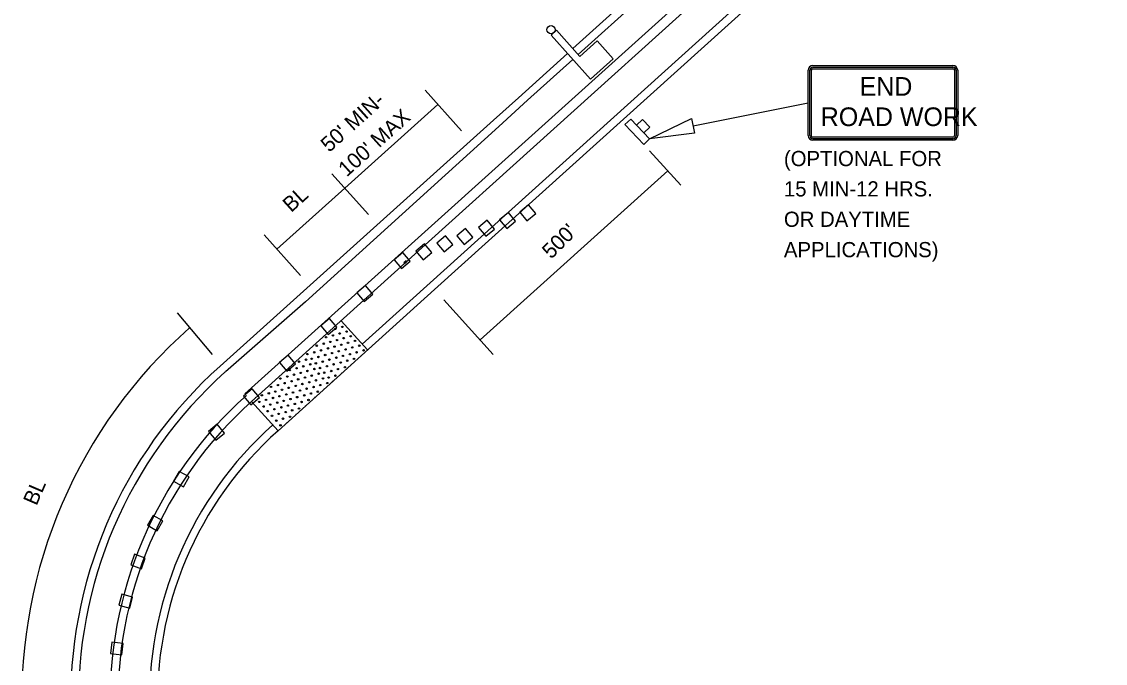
# Model space of a CAD drawing. Extents: x 1531.4 to 1538.6, y 1529.6 to 1539.7.
# Drawn here: x 1533.912 to 1538.193, y 1535.235 to 1537.771 of the extents above; entities that cross this region are included whole.
import ezdxf

# ---------------------------------------------------------------- set-up
doc = ezdxf.new("R2010")
doc.units = 0
for name, color, linetype in [('C-SIGN-FACE-N', 7, 'Continuous'), ('DETL-DIMS', 7, 'Continuous'), ('DETL-LINE', 7, 'Continuous'), ('DETL-NOTE', 7, 'Continuous')]:
    doc.layers.add(name, color=color, linetype=linetype)

msp = doc.modelspace()

# ---------------------------------------------------------------- linework, layer by layer
at = {"layer": 'C-SIGN-FACE-N'}
for p, q in [((1537.0377, 1537.5977), (1537.5916, 1537.5977)), ((1537.0377, 1537.5977), (1537.5916, 1537.5977)), ((1537.0377, 1537.5918), (1537.5916, 1537.5918)), ((1537.0377, 1537.5853), (1537.5916, 1537.5853)), ((1537.0194, 1537.3208), (1537.0194, 1537.5794)), ((1537.0253, 1537.3208), (1537.0253, 1537.5794)), ((1537.0318, 1537.3208), (1537.0318, 1537.5794)), ((1537.5975, 1537.5794), (1537.5975, 1537.3208)), ((1537.604, 1537.5794), (1537.604, 1537.3208)), ((1537.6099, 1537.5794), (1537.6099, 1537.3208)), ((1537.5916, 1537.3149), (1537.0377, 1537.3149)), ((1537.5916, 1537.3084), (1537.0377, 1537.3084)), ((1537.5916, 1537.3025), (1537.0377, 1537.3025))]:
    msp.add_line(p, q, dxfattribs=at)
for centre, radius, start, end in [((1537.0378, 1537.5793), 0.0185, 90, 180), ((1537.0378, 1537.5793), 0.0123, 90, 180), ((1537.0378, 1537.5793), 0.00615, 90, 180), ((1537.5914, 1537.5793), 0.0185, 0, 90), ((1537.5914, 1537.5793), 0.0123, 0, 90), ((1537.5914, 1537.5793), 0.00615, 0, 90), ((1537.0378, 1537.321), 0.0185, 180, 270), ((1537.0378, 1537.321), 0.0123, 180, 270), ((1537.0378, 1537.321), 0.00615, 180, 270), ((1537.5914, 1537.321), 0.0185, 270, 0), ((1537.5914, 1537.321), 0.0123, 270, 0), ((1537.5914, 1537.321), 0.00615, 270, 0)]:
    msp.add_arc(centre, radius, start, end, dxfattribs=at)
at = {"layer": 'DETL-DIMS'}
for p, q in [((1535.5054, 1537.5008), (1535.6495, 1537.3399)), ((1535.1882, 1537.1133), (1535.5561, 1537.4442)), ((1536.5642, 1537.3594), (1537.0194, 1537.4501)), ((1536.3924, 1537.2612), (1536.5157, 1537.1245)), ((1535.1375, 1537.1699), (1535.2816, 1537.009)), ((1535.7236, 1536.5133), (1536.4642, 1537.1817)), ((1534.9204, 1536.8724), (1535.1882, 1537.1133)), ((1534.8699, 1536.9288), (1535.0139, 1536.7678)), ((1535.58, 1536.6724), (1535.7751, 1536.4561)), ((1534.5257, 1536.6211), (1534.6645, 1536.4555))]:
    msp.add_line(p, q, dxfattribs=at)
msp.add_lwpolyline([(1536.5584, 1537.3888), (1536.5702, 1537.33), (1536.3921, 1537.3076)], close=True, dxfattribs=at)
msp.add_arc((1535.8737, 1535.091), 1.9621, 131.4354, 181.9604, dxfattribs=at)
at = {"layer": 'DETL-LINE'}
for p, q in [((1536.0895, 1537.6646), (1537.9623, 1539.3605)), ((1536.1102, 1537.6414), (1537.9832, 1539.3374)), ((1534.7936, 1536.3), (1538.0646, 1539.2471)), ((1535.4388, 1536.8288), (1538.0887, 1539.2203)), ((1535.2575, 1536.4968), (1538.1724, 1539.1276)), ((1535.5433, 1536.713), (1538.1933, 1539.1044)), ((1536.0037, 1537.7183), (1536.0248, 1537.7371)), ((1536.1593, 1537.544), (1536.0037, 1537.7183)), ((1536.0248, 1537.7371), (1536.1167, 1537.6341)), ((1536.1856, 1537.6956), (1536.1167, 1537.6341)), ((1536.2493, 1537.6244), (1536.1856, 1537.6956)), ((1535.875, 1537.4704), (1536.0685, 1537.6456)), ((1535.9104, 1537.4605), (1536.0893, 1537.6224)), ((1536.1593, 1537.544), (1536.2493, 1537.6244)), ((1535.7753, 1537.3814), (1535.875, 1537.4704)), ((1535.7968, 1537.3573), (1535.9104, 1537.4605)), ((1534.6953, 1536.4101), (1535.7753, 1537.3814)), ((1535.0336, 1536.6643), (1535.7968, 1537.3573)), ((1534.8202, 1536.2707), (1535.4388, 1536.8288)), ((1535.4206, 1536.8167), (1535.4206, 1536.8167)), ((1535.447, 1536.8244), (1535.447, 1536.8244)), ((1534.9247, 1536.1547), (1535.5433, 1536.713)), ((1535.2721, 1536.6827), (1535.2721, 1536.6827)), ((1535.0336, 1536.6643), (1534.7163, 1536.387)), ((1535.1511, 1536.5573), (1535.1511, 1536.5573)), ((1535.1737, 1536.5896), (1535.2782, 1536.4738)), ((1535.1782, 1536.5656), (1535.1782, 1536.5656)), ((1535.1787, 1536.565), (1535.1787, 1536.565)), ((1535.1143, 1536.5241), (1535.1143, 1536.5241)), ((1535.1143, 1536.5241), (1535.1143, 1536.5241)), ((1535.1247, 1536.5496), (1535.1247, 1536.5496)), ((1535.1408, 1536.5318), (1535.1408, 1536.5318)), ((1535.1413, 1536.5312), (1535.1413, 1536.5312)), ((1535.1574, 1536.5134), (1535.1574, 1536.5134)), ((1535.1579, 1536.5128), (1535.1579, 1536.5128)), ((1535.1677, 1536.5389), (1535.1677, 1536.5389)), ((1535.1844, 1536.5205), (1535.1844, 1536.5205)), ((1535.1948, 1536.5472), (1535.1948, 1536.5472)), ((1535.1953, 1536.5466), (1535.1953, 1536.5466)), ((1535.2119, 1536.5282), (1535.2119, 1536.5282)), ((1535.2119, 1536.5282), (1535.2119, 1536.5282)), ((1535.0775, 1536.4909), (1535.0775, 1536.4909)), ((1535.0941, 1536.4725), (1535.0941, 1536.4725)), ((1535.1045, 1536.4991), (1535.1045, 1536.4991)), ((1535.1051, 1536.4985), (1535.1051, 1536.4985)), ((1535.1212, 1536.4807), (1535.1212, 1536.4807)), ((1535.1217, 1536.4801), (1535.1217, 1536.4801)), ((1535.1309, 1536.5057), (1535.1309, 1536.5057)), ((1535.1309, 1536.5057), (1535.1309, 1536.5057)), ((1535.1475, 1536.4873), (1535.1475, 1536.4873)), ((1535.1475, 1536.4873), (1535.1475, 1536.4873)), ((1535.1642, 1536.4689), (1535.1642, 1536.4689)), ((1535.1642, 1536.4689), (1535.1642, 1536.4689)), ((1535.1745, 1536.4944), (1535.1745, 1536.4944)), ((1535.1745, 1536.4944), (1535.1745, 1536.4944)), ((1535.1911, 1536.476), (1535.1911, 1536.476)), ((1535.1911, 1536.476), (1535.1911, 1536.476)), ((1535.201, 1536.5021), (1535.201, 1536.5021)), ((1535.2176, 1536.4837), (1535.2176, 1536.4837)), ((1535.2286, 1536.5097), (1535.2286, 1536.5097)), ((1535.2286, 1536.5097), (1535.2286, 1536.5097)), ((1535.2452, 1536.4913), (1535.2452, 1536.4913)), ((1535.2457, 1536.4907), (1535.2457, 1536.4907)), ((1535.2618, 1536.4729), (1535.2618, 1536.4729)), ((1535.2623, 1536.4723), (1535.2623, 1536.4723)), ((1535.0076, 1536.4278), (1535.0076, 1536.4278)), ((1535.0346, 1536.436), (1535.0346, 1536.436)), ((1535.0351, 1536.4354), (1535.0351, 1536.4354)), ((1535.0407, 1536.4576), (1535.0407, 1536.4576)), ((1535.0407, 1536.4576), (1535.0407, 1536.4576)), ((1535.0573, 1536.4392), (1535.0573, 1536.4392)), ((1535.0573, 1536.4392), (1535.0573, 1536.4392)), ((1535.0671, 1536.4653), (1535.0671, 1536.4653)), ((1535.0677, 1536.4647), (1535.0677, 1536.4647)), ((1535.0837, 1536.4469), (1535.0837, 1536.4469)), ((1535.0843, 1536.4463), (1535.0843, 1536.4463)), ((1535.1009, 1536.4279), (1535.1009, 1536.4279)), ((1535.1009, 1536.4279), (1535.1009, 1536.4279)), ((1535.1107, 1536.454), (1535.1107, 1536.454)), ((1535.1273, 1536.4356), (1535.1273, 1536.4356)), ((1535.1383, 1536.4617), (1535.1383, 1536.4617)), ((1535.1383, 1536.4617), (1535.1383, 1536.4617)), ((1535.1549, 1536.4433), (1535.1549, 1536.4433)), ((1535.1549, 1536.4433), (1535.1549, 1536.4433)), ((1535.1808, 1536.4505), (1535.1808, 1536.4505)), ((1535.1808, 1536.4505), (1535.1808, 1536.4505)), ((1535.1979, 1536.4315), (1535.1979, 1536.4315)), ((1535.1979, 1536.4315), (1535.1979, 1536.4315)), ((1535.2078, 1536.4576), (1535.2078, 1536.4576)), ((1535.2083, 1536.457), (1535.2083, 1536.457)), ((1535.2244, 1536.4392), (1535.2244, 1536.4392)), ((1535.2249, 1536.4386), (1535.2249, 1536.4386)), ((1535.2347, 1536.4647), (1535.2347, 1536.4647)), ((1534.9707, 1536.3945), (1534.9707, 1536.3945)), ((1534.9707, 1536.3945), (1534.9707, 1536.3945)), ((1534.9811, 1536.42), (1534.9811, 1536.42)), ((1534.9972, 1536.4022), (1534.9972, 1536.4022)), ((1534.9977, 1536.4016), (1534.9977, 1536.4016)), ((1535.0138, 1536.3838), (1535.0138, 1536.3838)), ((1535.0143, 1536.3832), (1535.0143, 1536.3832)), ((1535.0242, 1536.4093), (1535.0242, 1536.4093)), ((1535.0408, 1536.3909), (1535.0408, 1536.3909)), ((1535.0512, 1536.4176), (1535.0512, 1536.4176)), ((1535.0518, 1536.417), (1535.0518, 1536.417)), ((1535.0684, 1536.3986), (1535.0684, 1536.3986)), ((1535.0684, 1536.3986), (1535.0684, 1536.3986)), ((1535.0739, 1536.4208), (1535.0739, 1536.4208)), ((1535.0739, 1536.4208), (1535.0739, 1536.4208)), ((1535.0905, 1536.4024), (1535.0905, 1536.4024)), ((1535.0905, 1536.4024), (1535.0905, 1536.4024)), ((1535.1071, 1536.384), (1535.1071, 1536.384)), ((1535.1071, 1536.384), (1535.1071, 1536.384)), ((1535.1175, 1536.4095), (1535.1175, 1536.4095)), ((1535.1175, 1536.4095), (1535.1175, 1536.4095)), ((1535.1341, 1536.3911), (1535.1341, 1536.3911)), ((1535.1347, 1536.3905), (1535.1347, 1536.3905)), ((1535.144, 1536.4172), (1535.144, 1536.4172)), ((1535.1611, 1536.3982), (1535.1611, 1536.3982)), ((1535.1715, 1536.4249), (1535.1715, 1536.4249)), ((1535.1721, 1536.4243), (1535.1721, 1536.4243)), ((1535.1882, 1536.4065), (1535.1882, 1536.4065)), ((1535.1887, 1536.4059), (1535.1887, 1536.4059)), ((1534.9336, 1536.361), (1534.9336, 1536.361)), ((1534.9502, 1536.3426), (1534.9502, 1536.3426)), ((1534.9607, 1536.3693), (1534.9607, 1536.3693)), ((1534.9612, 1536.3687), (1534.9612, 1536.3687)), ((1534.9773, 1536.3509), (1534.9773, 1536.3509)), ((1534.9778, 1536.3503), (1534.9778, 1536.3503)), ((1534.9874, 1536.3761), (1534.9874, 1536.3761)), ((1534.9874, 1536.3761), (1534.9874, 1536.3761)), ((1535.004, 1536.3577), (1535.004, 1536.3577)), ((1535.004, 1536.3577), (1535.004, 1536.3577)), ((1535.031, 1536.3648), (1535.031, 1536.3648)), ((1535.031, 1536.3648), (1535.031, 1536.3648)), ((1535.0476, 1536.3464), (1535.0476, 1536.3464)), ((1535.0476, 1536.3464), (1535.0476, 1536.3464)), ((1535.0574, 1536.3725), (1535.0574, 1536.3725)), ((1535.074, 1536.3541), (1535.074, 1536.3541)), ((1535.085, 1536.3802), (1535.085, 1536.3802)), ((1535.085, 1536.3802), (1535.085, 1536.3802)), ((1535.1016, 1536.3618), (1535.1016, 1536.3618)), ((1535.1021, 1536.3612), (1535.1021, 1536.3612)), ((1535.1182, 1536.3433), (1535.1182, 1536.3433)), ((1535.1188, 1536.3428), (1535.1188, 1536.3428)), ((1535.1243, 1536.365), (1535.1243, 1536.365)), ((1535.1243, 1536.365), (1535.1243, 1536.365)), ((1535.1507, 1536.3727), (1535.1507, 1536.3727)), ((1535.1513, 1536.3721), (1535.1513, 1536.3721)), ((1534.8875, 1536.3032), (1534.8875, 1536.3032)), ((1534.888, 1536.3026), (1534.888, 1536.3026)), ((1534.8968, 1536.3278), (1534.8968, 1536.3278)), ((1534.8968, 1536.3278), (1534.8968, 1536.3278)), ((1534.9134, 1536.3094), (1534.9134, 1536.3094)), ((1534.9134, 1536.3094), (1534.9134, 1536.3094)), ((1534.9233, 1536.3355), (1534.9233, 1536.3355)), ((1534.9238, 1536.3349), (1534.9238, 1536.3349)), ((1534.9399, 1536.3171), (1534.9399, 1536.3171)), ((1534.9404, 1536.3165), (1534.9404, 1536.3165)), ((1534.957, 1536.2981), (1534.957, 1536.2981)), ((1534.957, 1536.2981), (1534.957, 1536.2981)), ((1534.9669, 1536.3242), (1534.9669, 1536.3242)), ((1534.9835, 1536.3058), (1534.9835, 1536.3058)), ((1534.9944, 1536.3318), (1534.9944, 1536.3318)), ((1534.9944, 1536.3318), (1534.9944, 1536.3318)), ((1535.0111, 1536.3134), (1535.0111, 1536.3134)), ((1535.0111, 1536.3134), (1535.0111, 1536.3134)), ((1535.0206, 1536.3393), (1535.0206, 1536.3393)), ((1535.0206, 1536.3393), (1535.0206, 1536.3393)), ((1535.0372, 1536.3209), (1535.0372, 1536.3209)), ((1535.0372, 1536.3209), (1535.0372, 1536.3209)), ((1535.0544, 1536.3019), (1535.0544, 1536.3019)), ((1535.0544, 1536.3019), (1535.0544, 1536.3019)), ((1535.0642, 1536.328), (1535.0642, 1536.328)), ((1535.0647, 1536.3274), (1535.0647, 1536.3274)), ((1535.0808, 1536.3096), (1535.0808, 1536.3096)), ((1535.0813, 1536.309), (1535.0813, 1536.309)), ((1535.0912, 1536.3351), (1535.0912, 1536.3351)), ((1534.9247, 1536.1547), (1534.8202, 1536.2705)), ((1534.834, 1536.2872), (1534.834, 1536.2872)), ((1534.8501, 1536.2694), (1534.8501, 1536.2694)), ((1534.8506, 1536.2688), (1534.8506, 1536.2688)), ((1534.8604, 1536.295), (1534.8604, 1536.295)), ((1534.877, 1536.2765), (1534.877, 1536.2765)), ((1534.8937, 1536.2581), (1534.8937, 1536.2581)), ((1534.9041, 1536.2848), (1534.9041, 1536.2848)), ((1534.9046, 1536.2842), (1534.9046, 1536.2842)), ((1534.9212, 1536.2658), (1534.9212, 1536.2658)), ((1534.9212, 1536.2658), (1534.9212, 1536.2658)), ((1534.93, 1536.291), (1534.93, 1536.291)), ((1534.93, 1536.291), (1534.93, 1536.291)), ((1534.9466, 1536.2726), (1534.9466, 1536.2726)), ((1534.9466, 1536.2726), (1534.9466, 1536.2726)), ((1534.9736, 1536.2797), (1534.9736, 1536.2797)), ((1534.9736, 1536.2797), (1534.9736, 1536.2797)), ((1534.9903, 1536.2613), (1534.9903, 1536.2613)), ((1534.9908, 1536.2607), (1534.9908, 1536.2607)), ((1535.0001, 1536.2874), (1535.0001, 1536.2874)), ((1535.0172, 1536.2684), (1535.0172, 1536.2684)), ((1535.0277, 1536.295), (1535.0277, 1536.295)), ((1535.0282, 1536.2944), (1535.0282, 1536.2944)), ((1535.0443, 1536.2766), (1535.0443, 1536.2766)), ((1535.0448, 1536.276), (1535.0448, 1536.276)), ((1534.8667, 1536.251), (1534.8667, 1536.251)), ((1534.8672, 1536.2504), (1534.8672, 1536.2504)), ((1534.8838, 1536.232), (1534.8838, 1536.232)), ((1534.8838, 1536.232), (1534.8838, 1536.232)), ((1534.9004, 1536.2136), (1534.9004, 1536.2136)), ((1534.9004, 1536.2136), (1534.9004, 1536.2136)), ((1534.9103, 1536.2397), (1534.9103, 1536.2397)), ((1534.9269, 1536.2213), (1534.9269, 1536.2213)), ((1534.9379, 1536.2474), (1534.9379, 1536.2474)), ((1534.9379, 1536.2474), (1534.9379, 1536.2474)), ((1534.9545, 1536.229), (1534.9545, 1536.229)), ((1534.955, 1536.2284), (1534.955, 1536.2284)), ((1534.9633, 1536.2541), (1534.9633, 1536.2541)), ((1534.9633, 1536.2541), (1534.9633, 1536.2541)), ((1534.9804, 1536.2351), (1534.9804, 1536.2351)), ((1534.9804, 1536.2351), (1534.9804, 1536.2351)), ((1535.0069, 1536.2428), (1535.0069, 1536.2428)), ((1535.0074, 1536.2423), (1535.0074, 1536.2423)), ((1534.9171, 1536.1952), (1534.9171, 1536.1952)), ((1534.9176, 1536.1946), (1534.9176, 1536.1946)), ((1534.9337, 1536.1768), (1534.9337, 1536.1768)), ((1534.9342, 1536.1762), (1534.9342, 1536.1762)), ((1534.944, 1536.2023), (1534.944, 1536.2023)), ((1534.9711, 1536.2106), (1534.9711, 1536.2106)), ((1534.9716, 1536.21), (1534.9716, 1536.21))]:
    msp.add_line(p, q, dxfattribs=at)
for points in [[(1536.3179, 1537.3863), (1536.2954, 1537.3651), (1536.3696, 1537.2864), (1536.3921, 1537.3076)], [(1536.3409, 1537.3619), (1536.3693, 1537.3318), (1536.3931, 1537.3543), (1536.3647, 1537.3843)], [(1535.8794, 1537.0184), (1535.9082, 1536.9841), (1535.9425, 1537.0129), (1535.9137, 1537.0472)], [(1535.7166, 1536.9574), (1535.7454, 1536.9231), (1535.7797, 1536.9519), (1535.7509, 1536.9862)], [(1535.8002, 1536.9887), (1535.829, 1536.9544), (1535.8633, 1536.9832), (1535.8345, 1537.0175)], [(1535.6305, 1536.9252), (1535.6593, 1536.8909), (1535.6936, 1536.9197), (1535.6648, 1536.954)], [(1535.5523, 1536.8959), (1535.5811, 1536.8616), (1535.6154, 1536.8904), (1535.5866, 1536.9247)], [(1535.3835, 1536.8299), (1535.4124, 1536.7955), (1535.4467, 1536.8243), (1535.4178, 1536.8586)], [(1535.4688, 1536.8646), (1535.4976, 1536.8303), (1535.5319, 1536.8591), (1535.5031, 1536.8934)], [(1535.2363, 1536.6995), (1535.2652, 1536.6651), (1535.2995, 1536.6939), (1535.2706, 1536.7282)], [(1535.094, 1536.5691), (1535.1228, 1536.5347), (1535.1572, 1536.5635), (1535.1283, 1536.5978)], [(1534.9299, 1536.4242), (1534.9588, 1536.3898), (1534.9931, 1536.4186), (1534.9642, 1536.4529)], [(1534.7876, 1536.2913), (1534.8164, 1536.257), (1534.8507, 1536.2858), (1534.8219, 1536.3201)], [(1534.65, 1536.1513), (1534.6789, 1536.1169), (1534.7132, 1536.1457), (1534.6844, 1536.1801)], [(1534.5118, 1535.9555), (1534.5506, 1535.9331), (1534.573, 1535.9719), (1534.5342, 1535.9942)], [(1534.4081, 1535.7816), (1534.4469, 1535.7592), (1534.4693, 1535.798), (1534.4305, 1535.8203)], [(1534.3424, 1535.6246), (1534.3845, 1535.6093), (1534.3998, 1535.6514), (1534.3577, 1535.6666)], [(1534.2958, 1535.4649), (1534.3393, 1535.454), (1534.3501, 1535.4974), (1534.3067, 1535.5082)], [(1534.2625, 1535.2748), (1534.307, 1535.2692), (1534.3126, 1535.3136), (1534.2682, 1535.3192)]]:
    msp.add_lwpolyline(points, close=True, dxfattribs=at)
for points in [[(1535.4307, 1536.8256), (1535.4221, 1536.8179)], [(1535.2486, 1536.4469), (1535.251, 1536.4491)], [(1535.2117, 1536.4137), (1535.2142, 1536.4159)], [(1535.1381, 1536.3472), (1535.1405, 1536.3494)], [(1535.1749, 1536.3805), (1535.1773, 1536.3826)], [(1535.105, 1536.3174), (1535.1074, 1536.3196)], [(1535.0682, 1536.2842), (1535.0706, 1536.2864)], [(1534.9942, 1536.2174), (1534.9967, 1536.2196)], [(1535.0311, 1536.2506), (1535.0335, 1536.2528)], [(1534.9579, 1536.1846), (1534.9603, 1536.1868)]]:
    msp.add_lwpolyline(points, dxfattribs=at)
for centre, radius in [((1536.0031, 1537.7394), 0.0161), ((1535.1512, 1536.5573), 0.00291), ((1535.1787, 1536.565), 0.00291), ((1535.1143, 1536.5241), 0.00291), ((1535.1413, 1536.5312), 0.00291), ((1535.1579, 1536.5128), 0.00291), ((1535.1678, 1536.5389), 0.00291), ((1535.1844, 1536.5205), 0.00291), ((1535.1953, 1536.5465), 0.00291), ((1535.212, 1536.5281), 0.00291), ((1535.2286, 1536.5097), 0.00291), ((1535.0775, 1536.4908), 0.00291), ((1535.0941, 1536.4724), 0.00291), ((1535.1051, 1536.4985), 0.00291), ((1535.1217, 1536.4801), 0.00291), ((1535.1309, 1536.5057), 0.00291), ((1535.1476, 1536.4873), 0.00291), ((1535.1642, 1536.4688), 0.00291), ((1535.1745, 1536.4944), 0.00291), ((1535.1912, 1536.476), 0.00291), ((1535.201, 1536.5021), 0.00291), ((1535.2176, 1536.4837), 0.00291), ((1535.2457, 1536.4907), 0.00291), ((1535.2623, 1536.4723), 0.00291), ((1535.0076, 1536.4278), 0.00291), ((1535.0352, 1536.4354), 0.00291), ((1535.0407, 1536.4576), 0.00291), ((1535.0573, 1536.4392), 0.00291), ((1535.0676, 1536.4647), 0.00291), ((1535.0843, 1536.4463), 0.00291), ((1535.1009, 1536.4279), 0.00291), ((1535.1107, 1536.454), 0.00291), ((1535.1273, 1536.4356), 0.00291), ((1535.1383, 1536.4616), 0.00291), ((1535.1549, 1536.4432), 0.00291), ((1535.1721, 1536.4242), 0.00291), ((1535.1808, 1536.4504), 0.00291), ((1535.1979, 1536.4314), 0.00291), ((1535.2083, 1536.457), 0.00291), ((1535.2249, 1536.4385), 0.00291), ((1535.2348, 1536.4647), 0.00291), ((1534.9708, 1536.3945), 0.00291), ((1534.9978, 1536.4016), 0.00291), ((1535.0144, 1536.3832), 0.00291), ((1535.0242, 1536.4093), 0.00291), ((1535.0408, 1536.3909), 0.00291), ((1535.0518, 1536.417), 0.00291), ((1535.0684, 1536.3986), 0.00291), ((1535.0739, 1536.4208), 0.00291), ((1535.085, 1536.3802), 0.00291), ((1535.0905, 1536.4024), 0.00291), ((1535.1071, 1536.3839), 0.00291), ((1535.1175, 1536.4095), 0.00291), ((1535.1346, 1536.3905), 0.00291), ((1535.1439, 1536.4172), 0.00291), ((1535.1611, 1536.3982), 0.00291), ((1535.1887, 1536.4058), 0.00291), ((1534.9337, 1536.361), 0.00291), ((1534.9503, 1536.3426), 0.00291), ((1534.9612, 1536.3687), 0.00291), ((1534.9779, 1536.3503), 0.00291), ((1534.9874, 1536.3761), 0.00291), ((1535.004, 1536.3577), 0.00291), ((1535.0206, 1536.3393), 0.00291), ((1535.031, 1536.3648), 0.00291), ((1535.0476, 1536.3464), 0.00291), ((1535.0575, 1536.3725), 0.00291), ((1535.0741, 1536.3541), 0.00291), ((1535.1022, 1536.3612), 0.00291), ((1535.1188, 1536.3428), 0.00291), ((1535.1243, 1536.3649), 0.00291), ((1535.1513, 1536.3721), 0.00291), ((1534.8605, 1536.295), 0.00291), ((1534.8881, 1536.3026), 0.00291), ((1534.8968, 1536.3278), 0.00291), ((1534.9134, 1536.3094), 0.00291), ((1534.9238, 1536.3349), 0.00291), ((1534.9404, 1536.3165), 0.00291), ((1534.9571, 1536.2981), 0.00291), ((1534.9669, 1536.3242), 0.00291), ((1534.9835, 1536.3058), 0.00291), ((1534.9945, 1536.3318), 0.00291), ((1535.0111, 1536.3134), 0.00291), ((1535.0282, 1536.2944), 0.00291), ((1535.0373, 1536.3209), 0.00291), ((1535.0544, 1536.3019), 0.00291), ((1535.0648, 1536.3274), 0.00291), ((1535.0814, 1536.309), 0.00291), ((1535.0912, 1536.3351), 0.00291), ((1534.8506, 1536.2688), 0.00291), ((1534.8771, 1536.2766), 0.00291), ((1534.8937, 1536.2581), 0.00291), ((1534.9047, 1536.2842), 0.00291), ((1534.9213, 1536.2658), 0.00291), ((1534.9301, 1536.291), 0.00291), ((1534.9467, 1536.2725), 0.00291), ((1534.9633, 1536.2541), 0.00291), ((1534.9737, 1536.2797), 0.00291), ((1534.9908, 1536.2607), 0.00291), ((1535.0001, 1536.2874), 0.00291), ((1535.0173, 1536.2684), 0.00291), ((1535.0449, 1536.276), 0.00291), ((1534.8673, 1536.2504), 0.00291), ((1534.8839, 1536.232), 0.00291), ((1534.9005, 1536.2136), 0.00291), ((1534.9103, 1536.2397), 0.00291), ((1534.9269, 1536.2213), 0.00291), ((1534.9379, 1536.2474), 0.00291), ((1534.9551, 1536.2284), 0.00291), ((1534.9717, 1536.21), 0.00291), ((1534.9804, 1536.2351), 0.00291), ((1535.0074, 1536.2422), 0.00291), ((1534.9176, 1536.1946), 0.00291), ((1534.9343, 1536.1762), 0.00291), ((1534.9441, 1536.2023), 0.00291)]:
    msp.add_circle(centre, radius, dxfattribs=at)
for centre, radius, start, end in [((1535.4259, 1536.8223), 0.00582, 229.4612, 34.7887), ((1535.2514, 1536.4463), 0.00291, 97.9376, 166.1969), ((1535.8737, 1535.091), 1.7687, 131.7765, 181.9474), ((1535.8737, 1535.0911), 1.7376, 131.7684, 181.9568), ((1535.2146, 1536.413), 0.00291, 97.9376, 166.1969), ((1535.1409, 1536.3465), 0.00291, 97.9376, 166.1969), ((1535.1777, 1536.3798), 0.00291, 97.9376, 166.1969), ((1535.1078, 1536.3167), 0.00291, 97.9376, 166.1969), ((1535.8736, 1535.091), 1.6127, 131.7664, 182.0982), ((1535.8736, 1535.091), 1.5815, 131.7631, 182.1144), ((1535.071, 1536.2835), 0.00291, 97.9376, 166.1969), ((1534.9971, 1536.2167), 0.00291, 97.9376, 166.1969), ((1535.0339, 1536.25), 0.00291, 97.9376, 166.1969), ((1535.8735, 1535.0909), 1.4566, 131.7378, 182.3846), ((1534.9607, 1536.1839), 0.00291, 97.9376, 166.1969), ((1535.8736, 1535.091), 1.4254, 131.7347, 182.414)]:
    msp.add_arc(centre, radius, start, end, dxfattribs=at)

# ---------------------------------------------------------------- texts
at = {"layer": 'C-SIGN-FACE-N'}
for s, p in [('END', (1537.2225, 1537.4785)), ('ROAD WORK', (1537.069, 1537.3586))]:
    msp.add_text(s, height=0.07381, dxfattribs=at).set_placement(p)
at = {"layer": 'DETL-NOTE'}
for s, rotation, p in [("50' MIN-", 41.9657, (1535.1266, 1537.2522)), ("100' MAX", 41.9657, (1535.1961, 1537.1557)), ('BL', 42.1252, (1534.9764, 1537.015)), ("500'", 45, (1536.0037, 1536.8306)), ('BL', 66.7004, (1533.9702, 1535.8557))]:
    msp.add_text(s, height=0.06, rotation=rotation, dxfattribs=at).set_placement(p)
for s, p in [('(OPTIONAL FOR', (1536.9234, 1537.2004)), ('15 MIN-12 HRS. ', (1536.9234, 1537.0804)), ('OR DAYTIME', (1536.9234, 1536.9604)), ('APPLICATIONS)', (1536.9234, 1536.8404))]:
    msp.add_text(s, height=0.06, dxfattribs=at).set_placement(p)

doc.saveas('drawing.dxf')
